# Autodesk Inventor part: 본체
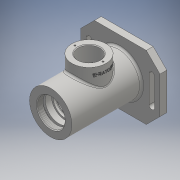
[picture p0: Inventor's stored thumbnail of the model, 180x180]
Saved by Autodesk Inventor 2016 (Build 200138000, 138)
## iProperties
Created: 2017-10
Part Number: 본체
Material: 일반
Document SubType Name: Modeling
Designer: USER
Density: 1 g/cm^3
Appearance: 기본값
Author: USER
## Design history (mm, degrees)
sketch "스케치1"
  geometry: C1 r 31 at (0, 0); 1 further point
  constraints: 1 centre point, 1 coincident
  dimensions: "d0" = 62 diameter of C1
extrude "돌출1" new body sketch "스케치1" distance "d1" = 102; taper "d2" = 0 deg
sketch "스케치2"
  geometry: L1 (-58, -47)-(58, -47); L2 (58, -47)-(58, 47); L3 (58, 47)-(-58, 47); L4 (-58, 47)-(-58, -47); C1 r 31 at (0, 0) reference; 2 further points
  constraints: 8 end point, 2 midpoint, 2 parallel, 1 horizontal, 1 horizontal alignment, 1 perpendicular, 1 vertical alignment
  dimensions: "d5" = 116 distance of L1.start L1.end; "d6" = 94 distance of L3.end L1.start
extrude "돌출2" join sketch "스케치2" distance "d7" = 10; taper "d8" = 0 deg
sketch "스케치3"
  geometry: C1 r 35 at (0, 0); 1 further point
  constraints: 1 centre point, 1 coincident
  dimensions: "d9" = 70 diameter of C1
extrude "돌출3" join sketch "스케치3" distance "d10" = 3; taper "d11" = 0 deg
node "작업 평면1"
sketch "스케치4"
  geometry: C1 r 25 at (0, 56); 1 further point
  constraints: 1 centre point, 1 vertical alignment
  dimensions: "d13" = 50 diameter of C1; "d14" = 56 distance of point (0, 0) C1.centre
extrude "돌출4" join sketch "스케치4" distance "d15" = 31.25; taper "d16" = 0 deg
sketch "스케치5"
  geometry: L1 (0, 0)-(128.633, 0); L2 (115, -35)-(115, 35) reference; L3 (101.7, 14.062)-(101.7, 12.904); L4 (101.7, 12.904)-(101, 12.5); L5 (101, 12.5)-(94, 12.5); L6 (93.7, 12.2)-(93.7, 10); L7 (93.7, 10)-(91, 10); L8 (91, 10)-(91, 13.5); L9 (88, 16.5)-(86, 16.5); L10 (86, 16.5)-(86, 17.2); L11 (85.7, 17.5)-(76, 17.5); L12 (75, 18.5)-(75, 23); L13 (72, 26)-(40, 26); L14 (37, 23)-(37, 18.5); L15 (103.466, 16.797)-(115, 22); L16 (36, 17.5)-(26, 17.5); L17 (26, 17.5)-(26, 18.5); L18 (26, 18.5)-(24.25, 18.5); L19 (21, 17.5)-(21, 20); L20 (21, 20)-(12, 20); L21 (12, 20)-(12, 24); L22 (12, 24)-(9, 24); L23 (9, 24)-(9, 0); L24 (21, 17.5)-(24.25, 17.5); L25 (24.25, 17.5)-(24.25, 18.5); L26 (0, 31)-(0, -31) reference; L27 (9, 0)-(115, 0); L28 (115, 22)-(115, 0); L29 (37, 18.5)-(36, 17.5); L30 (76, 17.5)-(75, 18.5); A1 r 0.3 centre (94, 12.2) between (94, 12.5) and (93.7, 12.2); A2 r 0.3 centre (85.7, 17.2) between (86, 17.2) and (85.7, 17.5); A3 r 3 centre (104.7, 14.062) between (103.466, 16.797) and (101.7, 14.062); A4 r 3 centre (88, 13.5) between (91, 13.5) and (88, 16.5); A5 r 3 centre (72, 23) between (75, 23) and (72, 26); A6 r 3 centre (40, 23) between (40, 26) and (37, 23); 8 further points
  constraints: 56 end point, 18 point on line, 17 perpendicular, 12 point on circle, 12 tangent, 6 centre point, 4 equal radius, 3 horizontal, 1 collinear, 1 horizontal alignment, 1 midpoint, 1 parallel
  dimensions: "d17" = 30 deg angle of L5 L4; "d20" = 32 diameter of point (101.7, 16) L1; "d21" = 0.7 horizontal distance of L3.end L4.end; "d22" = 44 diameter of L15.end L1; "d24" = 52 diameter of L13 L1; "d25" = 35 diameter of L11 L1; "d26" = 33 diameter of L9 L1; "d27" = 38 distance of point (75, 26) point (37, 26); "d28" = 5 distance between parallel lines of L8 L10; "d30" = 2.7 distance of L6.end L7.end; "d31" = 20 diameter of L7 L1; "d32" = 25 diameter of L5 L1; "d33" = 11 distance of point (86, 17.5) point (75, 17.5); "d34" = 35 diameter of L16 L1; "d35" = 11 distance of point (37, 17.5) L16.end; "d36" = 3 distance of L21.end L22.end; "d37" = 48 diameter of L22 L1; "d38" = 40 diameter of L20 L1; "d39" = 35 diameter of L24 L1; "d40" = 37 diameter of L18 L1; "d41" = 1.75 distance of L17.end L18.end; "d42" = 12 distance between parallel lines of L21 L26; "d43" = 21 distance between parallel lines of L26 L19; "d47" = 7.3 distance of L4.end point (93.7, 12.5); "d48" = 24 distance between parallel lines of L2 L8; "d49" = 0.3 radius of A1; "d50" = 3 radius of A3; "d51" = 1 distance of L14.end point (37, 17.5); "d52" = 1 distance of L16.start point (37, 17.5) (= d51); "d53" = 1 distance of L11.end point (75, 17.5) (= d51); "d54" = 1 distance of L12.start point (75, 17.5) (= d53)
revolve "회전1" sketch "스케치5" stored, may be unused: angle "d44" = 90 deg
sketch "스케치6"
  geometry: C1 r 31 at (0, 0) reference; 2 further points
  constraints: 1 coincident
hole "구멍1" sketch "스케치6" at (0, 0) diameter "d55" = 40.376; stored, may be unused: countersink angle "d59" = 90 deg, drill point angle "d61" = 0 deg; dims "d56" = 84, "d57" = 4, "d58" = 2, "d60" = 9
sketch "스케치7"
  geometry: C1 r 25 at (0, 0) reference; C2 r 16 at (0, 0); 1 further point
  constraints: 1 centre point, 1 coincident
  dimensions: "d62" = 32 diameter of C2
extrude "돌출5" cut sketch "스케치7" distance "d63" = 39.25; taper "d64" = 0 deg
sketch "스케치8"
  geometry: C1 r 16 at (0, 0) reference; 3 further points
  constraints: 3 horizontal alignment
  dimensions: "d65" = 41 distance of point (20.5, 0) point (-20.5, 0); "d66" = 20.5 distance of point (-20.5, 0) C1.centre
hole "구멍2" sketch "스케치8" at (20.5, 0), (-20.5, 0) diameter "d67" = 2.459; stored, may be unused: countersink angle "d71" = 90 deg, drill point angle "d73" = 118 deg; dims "d68" = 6, "d69" = 4, "d70" = 2, "d72" = 8
node "작업 평면2"
sketch "스케치9"
  geometry: L1 (0, 31)-(0, -31) reference; L2 (31, 47)-(81, 47) reference; 2 further points
  constraints: 1 other
  dimensions: "d75" = 56 distance from line of point (56, 37) L1; "d76" = 10 distance from line of point (56, 37) L2
feature "엠보싱1" sketch "스케치9" dims "d77" = 0.5, "d78" = 0
chamfer "모따기1" distance "d79" = 20; stored, may be unused: second distance "d80" = 2, angle "d81" = 45 deg
sketch "스케치10"
  geometry: L1 (46, 20)-(46, -20); L2 (42, 20)-(42, -20); L3 (50, -20)-(50, 20); L4 (-46, 20)-(-46, -20); L5 (-50, 20)-(-50, -20); L6 (-42, -20)-(-42, 20); A1 r 4 centre (46, 20) between (50, 20) and (42, 20); A2 r 4 centre (46, -20) between (42, -20) and (50, -20); A3 r 4 centre (-46, 20) between (-42, 20) and (-50, 20); A4 r 4 centre (-46, -20) between (-50, -20) and (-42, -20); 3 further points
  constraints: 16 end point, 8 point on circle, 8 tangent, 4 centre point, 3 parallel, 2 horizontal alignment, 2 midpoint, 1 vertical
  dimensions: "d82" = 46 distance from line of point (0, 0) L1; "d83" = 46 distance of point (-46, 0) point (0, 0); "d84" = 4 radius of A2; "d85" = 4 radius of A4; "d86" = 40 distance of L4.start L4.end; "d87" = 40 distance of L1.start L1.end
extrude "돌출6" cut sketch "스케치10" distance "d88" = 39.25; taper "d89" = 0 deg
fillet "모깎기1" dims "d90" = 3
chamfer "모따기2" distance "d91" = 1; stored, may be unused: second distance "d92" = 2, angle "d93" = 45 deg
chamfer "모따기3" distance "d94" = 1; stored, may be unused: second distance "d95" = 2, angle "d96" = 45 deg
node "솔리드1"
node "투영된 루프1"
other parameters: "d12" = 47, "d74" = 25
